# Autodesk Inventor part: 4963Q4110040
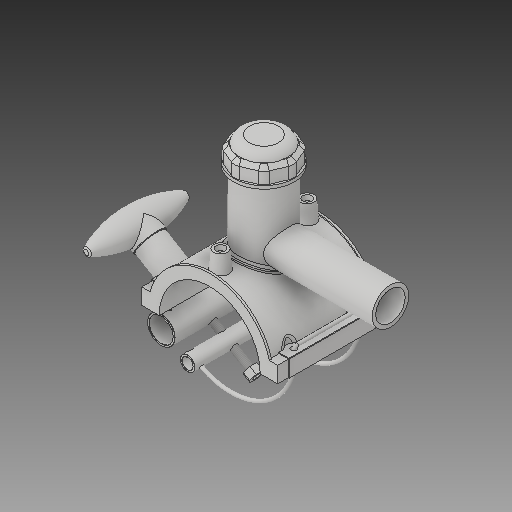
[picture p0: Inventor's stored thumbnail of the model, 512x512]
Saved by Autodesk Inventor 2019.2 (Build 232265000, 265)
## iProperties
Created: 2017-07
Part Number: 4963Q4110040
Material: Generic
Description: PLASSON TAPPING SADDLE 110x40
Document SubType Name: Modeling
Designer: KIM
Mass: 1712.7 g
Surface Area: 2671.49 cm^2
Volume: 1712.7 cm^3
Density: 1 g/cm^3
Appearance: Default
Author: KIM
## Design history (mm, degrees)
derived "4963Q4 (new clamping).ipt"
feature "Solid1::4963Q4 (new clamping).ipt"
feature "Solid2::4963Q4 (new clamping).ipt"
feature "Solid4::4963Q4 (new clamping).ipt"
feature "Solid5::4963Q4 (new clamping).ipt"
feature "Solid6::4963Q4 (new clamping).ipt"
feature "Solid7::4963Q4 (new clamping).ipt"
feature "Solid8::4963Q4 (new clamping).ipt"
feature "Solid9::4963Q4 (new clamping).ipt" dims "d70" = 15
feature "Solid10::4963Q4 (new clamping).ipt"
tag "TaggingFeature1"
body "Solid1"
body "Solid2"
body "Solid3"
body "Solid4"
body "Solid5"
body "Solid6"
body "Solid7"
other parameters: "d2" = 148, "d4" = 118, "d5" = 0, "d6" = 0.1, "d8" = 0, "d19" = 6, "d20" = 6, "d21" = 70.8, "d23" = 0, "d24" = 35.4, "d40" = 68.64, "d41" = 66, "d43" = 0, "d45" = 0, "d47" = 136.8, "d72" = 0, "d73" = 6, "d77" = 5.5, "d78" = 85, "d79" = 15, "d80" = 47.2, "d82" = 5 deg, "d84" = 4, "d85" = 14, "d86" = 0, "d87" = 3, "d88" = 0, "d89" = 1, "d90" = 1, "d91" = 94.4, "d92" = 0, "d93" = 0.5, "d94" = 57.89474, "d96" = 134.64, "d97" = 2.36, "d98" = 0, "d102" = 1.1, "d120" = 140 deg, "d121" = 24.228, "d122" = 20 deg, "d123" = 264, "d124" = 79.2, "d126" = 0, "d143" = 113.3, "d145" = 16.92308, "d149" = 1.65, "d150" = 18.61538, "d153" = 118, "d154" = 0, "d156" = 66, "d157" = 160 deg, "d159" = 4.4, "d161" = 1.65, "d162" = 70.8, "d163" = 0, "d164" = 55, "d167" = 11, "d168" = 64.39024, "d170" = 3.75, "d172" = 0, "d173" = 1, "d175" = 55, "d176" = 20 deg, "d177" = 7.7, "d178" = 22, "d180" = 0, "d183" = 8.8, "d184" = 6.16, "d185" = 38.35, "d186" = 38.35, "d187" = 66, "d188" = 6.6, "d189" = 7.7, "d190" = 0, "d191" = 99, "d193" = 7, "d194" = 4.13, "d195" = 90 deg, "d197" = 0, "d199" = 0, "d200" = 11, "d203" = 114, "d204" = 62.7, "d205" = 46.2, "d206" = 56.1, "d207" = 85.5, "d208" = 88.92, "d209" = 106.02, "d210" = 56.76, "d211" = 66, "d212" = 52.8, "d213" = 0.9, "d216" = 0, "d217" = 11, "d218" = 11, "d219" = 2.2, "d224" = 0, "d230" = 4.4, "d245" = 35.4, "d246" = 35.4, "d247" = 6, "d248" = 6, "d257" = 76, "d258" = 138, "d259" = 32, "d263" = 148, "d265" = 0, "d267" = 13.00006, "d268" = 2.60001, "d269" = 2.60001, "d271" = 2.60001, "d273" = 0, "d274" = 23.56194, "d275" = 88, "d277" = 44, "d278" = 176, "d280" = 0, "d283" = 0, "d285" = 0, "d286" = 17.5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
